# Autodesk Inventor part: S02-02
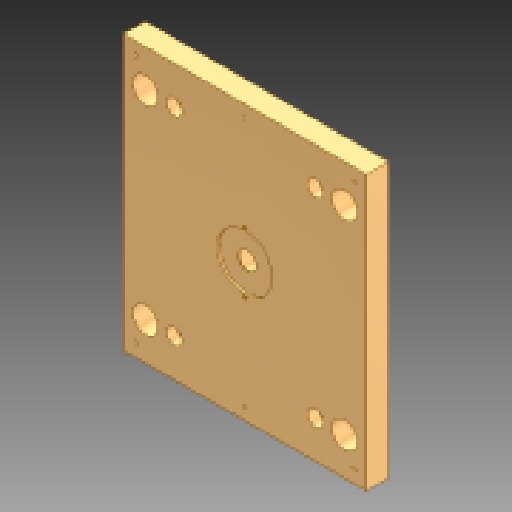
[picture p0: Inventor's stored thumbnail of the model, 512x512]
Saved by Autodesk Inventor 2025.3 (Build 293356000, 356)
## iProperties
Created: 2025-04
Part Number: S02-02
Material: Všeobecné
Document SubType Name: Modeling
Designer: Patrik
Density: 1 g/cm^3
Appearance: Výchozí
Description: Deska opěrná pravá
Stock Number: F 10 /396 396/ 36/1730
Mass: 6033.9 g
Surface Area: 4352.43 cm^2
Volume: 6033.9 cm^3
User Status: 1730
Author: Patrik
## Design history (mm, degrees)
feature "Base1"
feature "Vyřezání2"
feature "Vyřezání3"
sketch "Náčrt3"
  geometry: C1 r 19.55 at (0, 0) reference; 1 further point
extrude "Vysunutí3" cut sketch "Náčrt3" stored distance "d4" = 10; taper "d5" = 0 deg
sketch "Náčrt4"
  geometry: C1 r 4 at (0, 0) reference; 1 further point
extrude "Vysunutí4" cut sketch "Náčrt4" stored distance "d6" = 10; taper "d7" = 0 deg
feature "Vyřezání4"
sketch "Náčrt5"
  geometry: C1 r 8 at (18.295, 223.094) reference; 1 further point
hole "Díra1" sketch "Náčrt5" at (18.295, 223.094) diameter "d8" = 13.835; stored, may be unused: countersink angle "d12" = 90 deg, drill point angle "d14" = 118 deg; dims "d9" = 20, "d10" = 4, "d11" = 2, "d13" = 25
chamfer "Zkosení1" distance "d15" = 1; stored, may be unused: second distance "d16" = 2, angle "d17" = 45 deg
sketch "Náčrt6"
  geometry: C1 r 3 at (20, -426) reference; C2 r 3 at (20, -20) reference; C3 r 3 at (198, -20) reference; C4 r 3 at (376, -20) reference; C5 r 3 at (376, -426) reference; C6 r 3 at (198, -426) reference; 1 further point
hole "Díra2" sketch "Náčrt6" at (20, -426), (198, -426), (20, -20), (198, -20), (376, -20), (376, -426) diameter "d18" = 4.917; stored, may be unused: countersink angle "d22" = 90 deg, drill point angle "d24" = 118 deg; dims "d19" = 5, "d20" = 4, "d21" = 2, "d23" = 8
feature "Vyřezání5"
sketch "Náčrt7"
  geometry: C1 r 3 at (198.12, -272) reference; C2 r 3 at (197.88, -174) reference; 1 further point
hole "Díra3" sketch "Náčrt7" at (198.12, -272), (197.88, -174) diameter "d25" = 4.917; stored, may be unused: countersink angle "d29" = 90 deg, drill point angle "d31" = 118 deg; dims "d26" = 2, "d27" = 4, "d28" = 2, "d30" = 5
node "Těleso1"
node "Promítnutá smyčka1"
feature "Plocha2"
node "Povrch2"
feature "Plocha3"
node "Povrch3"
feature "Plocha4"
node "Povrch4"
feature "Plocha5"
node "Povrch5"
